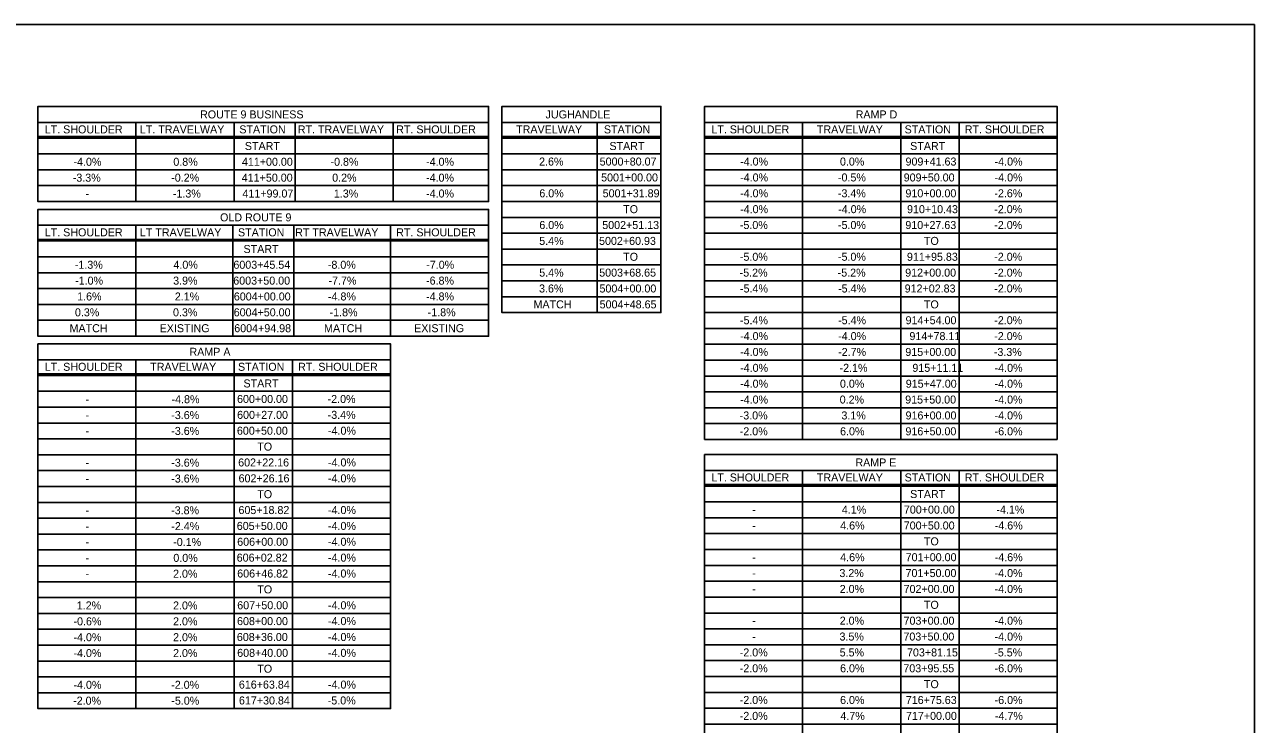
# Model space of a CAD drawing. Extents: x -15318841 to 1762012, y 465773 to 3693661.
# Drawn here: x -15314043.3 to -15313582.2, y 3693398.6 to 3693660.7 of the extents above; entities that cross this region are included whole.
import ezdxf

# ---------------------------------------------------------------- set-up
doc = ezdxf.new("R2010")
doc.units = 0
for name, color, linetype in [('BORDER', 7, 'Continuous'), ('Default', 7, 'Continuous'), ('DIMENSIONS', 7, 'Continuous')]:
    doc.layers.add(name, color=color, linetype=linetype)

msp = doc.modelspace()

# ---------------------------------------------------------------- linework, layer by layer
at = {"layer": 'BORDER'}
for p, q in [((-15314001.5, 3693624.08), (-15314001.5, 3693594.43)), ((-15313964.73, 3693624.08), (-15313964.73, 3693594.43)), ((-15313941.85, 3693624.08), (-15313941.85, 3693594.43)), ((-15313905.08, 3693624.08), (-15313905.08, 3693594.43)), ((-15313905.08, 3693624.08), (-15313905.08, 3693594.43)), ((-15313864.32, 3693624.08), (-15313864.32, 3693552.83)), ((-15313828.55, 3693624.08), (-15313828.55, 3693552.83)), ((-15313804.67, 3693624.08), (-15313804.67, 3693552.83)), ((-15313788.34, 3693624.08), (-15313788.34, 3693505.88)), ((-15313751.57, 3693624.08), (-15313751.57, 3693505.29)), ((-15313714.8, 3693624.08), (-15313714.8, 3693505.29)), ((-15313692.92, 3693624.08), (-15313692.92, 3693505.29)), ((-15314038.26, 3693618.8), (-15313869.32, 3693618.8)), ((-15314038.26, 3693618.2), (-15313869.32, 3693618.2)), ((-15313864.32, 3693618.8), (-15313804.67, 3693618.8)), ((-15313864.32, 3693618.2), (-15313804.67, 3693618.2)), ((-15313788.34, 3693618.8), (-15313656.16, 3693618.8)), ((-15313788.34, 3693618.2), (-15313656.16, 3693618.2)), ((-15314038.26, 3693612.26), (-15313869.32, 3693612.26)), ((-15314038.26, 3693612.26), (-15313869.32, 3693612.26)), ((-15314038.26, 3693612.26), (-15313869.32, 3693612.26)), ((-15313864.32, 3693612.26), (-15313804.67, 3693612.26)), ((-15313864.32, 3693612.26), (-15313804.67, 3693612.26)), ((-15313864.32, 3693612.26), (-15313804.67, 3693612.26)), ((-15313788.34, 3693612.26), (-15313656.16, 3693612.26)), ((-15313788.34, 3693612.26), (-15313656.16, 3693612.26)), ((-15313788.34, 3693612.26), (-15313656.16, 3693612.26)), ((-15314038.26, 3693606.32), (-15313869.32, 3693606.32)), ((-15313864.32, 3693606.32), (-15313804.67, 3693606.32)), ((-15313788.34, 3693606.32), (-15313656.16, 3693606.32)), ((-15314038.26, 3693600.38), (-15313869.32, 3693600.38)), ((-15313864.32, 3693600.38), (-15313804.67, 3693600.38)), ((-15313788.34, 3693600.38), (-15313656.16, 3693600.38)), ((-15313864.32, 3693594.43), (-15313804.67, 3693594.43)), ((-15313788.34, 3693594.43), (-15313656.16, 3693594.43)), ((-15313864.32, 3693588.49), (-15313804.67, 3693588.49)), ((-15313788.34, 3693588.49), (-15313656.16, 3693588.49)), ((-15314001.5, 3693585.52), (-15314001.5, 3693543.99)), ((-15313965.23, 3693585.52), (-15313965.23, 3693543.99)), ((-15313942.35, 3693585.52), (-15313942.35, 3693543.99)), ((-15313906.08, 3693585.52), (-15313906.08, 3693543.99)), ((-15314038.26, 3693580.24), (-15313869.32, 3693580.24)), ((-15314038.26, 3693579.64), (-15313869.32, 3693579.64)), ((-15313864.32, 3693582.55), (-15313804.67, 3693582.55)), ((-15313788.34, 3693582.55), (-15313656.16, 3693582.55)), ((-15314038.26, 3693573.7), (-15313869.32, 3693573.7)), ((-15314038.26, 3693573.7), (-15313869.32, 3693573.7)), ((-15314038.26, 3693573.7), (-15313869.32, 3693573.7)), ((-15313864.32, 3693576.6), (-15313804.67, 3693576.6)), ((-15313788.34, 3693576.6), (-15313656.16, 3693576.6)), ((-15313864.32, 3693570.66), (-15313804.67, 3693570.66)), ((-15313788.34, 3693570.66), (-15313656.16, 3693570.66)), ((-15314038.26, 3693567.76), (-15313869.32, 3693567.76)), ((-15313864.32, 3693564.72), (-15313804.67, 3693564.72)), ((-15313788.34, 3693564.72), (-15313656.16, 3693564.72)), ((-15314038.26, 3693561.81), (-15313869.32, 3693561.81)), ((-15314038.26, 3693555.87), (-15313869.32, 3693555.87)), ((-15313864.32, 3693558.78), (-15313804.67, 3693558.78)), ((-15313788.34, 3693558.78), (-15313656.16, 3693558.78)), ((-15313788.34, 3693552.83), (-15313656.16, 3693552.83)), ((-15314038.26, 3693549.93), (-15313869.32, 3693549.93)), ((-15313788.34, 3693546.89), (-15313656.16, 3693546.89)), ((-15313788.34, 3693540.95), (-15313656.16, 3693540.95)), ((-15314038.26, 3693535.16), (-15314038.26, 3693416.96)), ((-15314001.5, 3693535.16), (-15314001.5, 3693404.48)), ((-15313964.73, 3693535.16), (-15313964.73, 3693404.48)), ((-15313942.85, 3693535.16), (-15313942.85, 3693404.48)), ((-15313906.08, 3693535.16), (-15313906.08, 3693404.48)), ((-15313788.34, 3693535.01), (-15313656.16, 3693535.01)), ((-15314038.26, 3693529.87), (-15313906.08, 3693529.87)), ((-15314038.26, 3693529.28), (-15313906.08, 3693529.28)), ((-15313788.34, 3693529.06), (-15313656.16, 3693529.06)), ((-15314038.26, 3693523.34), (-15313906.08, 3693523.34)), ((-15314038.26, 3693523.34), (-15313906.08, 3693523.34)), ((-15314038.26, 3693523.34), (-15313906.08, 3693523.34)), ((-15313788.34, 3693523.12), (-15313656.16, 3693523.12)), ((-15314038.26, 3693517.39), (-15313906.08, 3693517.39)), ((-15313788.34, 3693517.18), (-15313656.16, 3693517.18)), ((-15314038.26, 3693511.45), (-15313906.08, 3693511.45)), ((-15313788.34, 3693511.24), (-15313656.16, 3693511.24)), ((-15314038.26, 3693505.51), (-15313906.08, 3693505.51)), ((-15314038.26, 3693499.57), (-15313906.08, 3693499.57)), ((-15314038.26, 3693493.62), (-15313906.08, 3693493.62)), ((-15313788.34, 3693493.72), (-15313788.34, 3693375.52)), ((-15313751.57, 3693493.72), (-15313751.57, 3693339.28)), ((-15313714.8, 3693493.72), (-15313714.8, 3693339.28)), ((-15313692.92, 3693493.72), (-15313692.92, 3693339.28)), ((-15314038.26, 3693487.68), (-15313906.08, 3693487.68)), ((-15313788.34, 3693488.44), (-15313656.16, 3693488.44)), ((-15313788.34, 3693487.84), (-15313656.16, 3693487.84)), ((-15314038.26, 3693481.74), (-15313906.08, 3693481.74)), ((-15313788.34, 3693481.9), (-15313656.16, 3693481.9)), ((-15313788.34, 3693481.9), (-15313656.16, 3693481.9)), ((-15313788.34, 3693481.9), (-15313656.16, 3693481.9)), ((-15314038.26, 3693475.79), (-15313906.08, 3693475.79)), ((-15313788.34, 3693475.96), (-15313656.16, 3693475.96)), ((-15314038.26, 3693469.85), (-15313906.08, 3693469.85)), ((-15313788.34, 3693470.02), (-15313656.16, 3693470.02)), ((-15314038.26, 3693463.91), (-15313906.08, 3693463.91)), ((-15313788.34, 3693464.07), (-15313656.16, 3693464.07)), ((-15313788.34, 3693458.13), (-15313656.16, 3693458.13)), ((-15314038.26, 3693457.97), (-15313906.08, 3693457.97)), ((-15314038.26, 3693452.02), (-15313906.08, 3693452.02)), ((-15313788.34, 3693452.19), (-15313656.16, 3693452.19)), ((-15314038.26, 3693446.08), (-15313906.08, 3693446.08)), ((-15313788.34, 3693446.24), (-15313656.16, 3693446.24)), ((-15314038.26, 3693440.14), (-15313906.08, 3693440.14)), ((-15313788.34, 3693440.3), (-15313656.16, 3693440.3)), ((-15314038.26, 3693434.2), (-15313906.08, 3693434.2)), ((-15313788.34, 3693434.36), (-15313656.16, 3693434.36)), ((-15314038.26, 3693428.25), (-15313906.08, 3693428.25)), ((-15313788.34, 3693428.42), (-15313656.16, 3693428.42)), ((-15314038.26, 3693422.31), (-15313906.08, 3693422.31)), ((-15313788.34, 3693422.47), (-15313656.16, 3693422.47)), ((-15314038.26, 3693416.37), (-15313906.08, 3693416.37)), ((-15313788.34, 3693416.53), (-15313656.16, 3693416.53)), ((-15314038.26, 3693410.42), (-15313906.08, 3693410.42)), ((-15313788.34, 3693410.59), (-15313656.16, 3693410.59)), ((-15313788.34, 3693404.65), (-15313656.16, 3693404.65)), ((-15313788.34, 3693398.7), (-15313656.16, 3693398.7))]:
    msp.add_line(p, q, dxfattribs=at)
for points in [[(-15314038.26, 3693624.08), (-15314038.26, 3693630.02), (-15313869.32, 3693630.02), (-15313869.32, 3693624.08)], [(-15313864.32, 3693624.08), (-15313864.32, 3693630.02), (-15313804.67, 3693630.02), (-15313804.67, 3693624.08)], [(-15313788.34, 3693624.08), (-15313788.34, 3693630.02), (-15313656.16, 3693630.02), (-15313656.16, 3693624.08)], [(-15314038.26, 3693585.52), (-15314038.26, 3693591.46), (-15313869.32, 3693591.46), (-15313869.32, 3693585.52)], [(-15314038.26, 3693535.16), (-15314038.26, 3693541.1), (-15313906.08, 3693541.1), (-15313906.08, 3693535.16)], [(-15313788.34, 3693493.72), (-15313788.34, 3693499.66), (-15313656.16, 3693499.66), (-15313656.16, 3693493.72)]]:
    msp.add_lwpolyline(points, dxfattribs=at)
for points in [[(-15314038.26, 3693624.08), (-15313869.32, 3693624.08), (-15313869.32, 3693594.43), (-15314038.26, 3693594.43)], [(-15313864.32, 3693624.08), (-15313804.67, 3693624.08), (-15313804.67, 3693552.83), (-15313864.32, 3693552.83)], [(-15313788.34, 3693624.08), (-15313656.16, 3693624.08), (-15313656.16, 3693505.29), (-15313788.34, 3693505.29)], [(-15314038.26, 3693585.52), (-15313869.32, 3693585.52), (-15313869.32, 3693543.99), (-15314038.26, 3693543.99)], [(-15314038.26, 3693535.16), (-15313906.08, 3693535.16), (-15313906.08, 3693404.48), (-15314038.26, 3693404.48)], [(-15313788.34, 3693493.72), (-15313656.16, 3693493.72), (-15313656.16, 3693339.28), (-15313788.34, 3693339.28)]]:
    msp.add_lwpolyline(points, close=True, dxfattribs=at)
at = {"layer": 'Default'}
msp.add_lwpolyline([(-15314452.76, 3693660.68), (-15313582.2, 3693660.68), (-15313582.2, 3693071.2), (-15314452.76, 3693071.2)], close=True, dxfattribs=at)

# ---------------------------------------------------------------- texts
at = {"layer": 'DIMENSIONS'}
for s, p in [('ROUTE 9 BUSINESS', (-15313977.48, 3693625.55)), ('JUGHANDLE', (-15313847.94, 3693625.55)), ('RAMP D', (-15313731.68, 3693625.55)), ('LT. SHOULDER', (-15314035.71, 3693619.94)), ('LT. TRAVELWAY', (-15314000.04, 3693619.94)), ('STATION', (-15313962.76, 3693619.94)), ('RT. TRAVELWAY', (-15313940.83, 3693619.94)), ('RT. SHOULDER', (-15313903.96, 3693619.94)), ('TRAVELWAY', (-15313858.99, 3693619.94)), ('STATION', (-15313826.08, 3693619.94)), ('LT. SHOULDER', (-15313785.78, 3693619.94)), ('TRAVELWAY', (-15313746.24, 3693619.94)), ('STATION', (-15313713.34, 3693619.94)), ('RT. SHOULDER', (-15313690.8, 3693619.94)), ('START', (-15313960.69, 3693613.72)), ('START', (-15313824.01, 3693613.72)), ('START', (-15313711.26, 3693613.72)), ('-4.0%', (-15314024.93, 3693607.81)), ('0.8%', (-15313987.5, 3693607.81)), ('411+00.00', (-15313961.79, 3693607.81)), ('-0.8%', (-15313928.57, 3693607.81)), ('-4.0%', (-15313892.75, 3693607.81)), ('2.6%', (-15313850.37, 3693607.89)), ('5000+80.07', (-15313827.66, 3693607.89)), ('-4.0%', (-15313775, 3693607.89)), ('0.0%', (-15313737.58, 3693607.89)), ('909+41.63', (-15313712.99, 3693607.89)), ('-4.0%', (-15313679.59, 3693607.89)), ('-3.3%', (-15314025.21, 3693601.86)), ('-0.2%', (-15313988.3, 3693601.86)), ('411+50.00', (-15313961.84, 3693601.86)), ('0.2%', (-15313927.95, 3693601.86)), ('-4.0%', (-15313892.75, 3693601.86)), ('5001+00.00', (-15313827.12, 3693601.94)), ('-4.0%', (-15313775, 3693601.94)), ('-0.5%', (-15313738.33, 3693601.94)), ('909+50.00', (-15313713.68, 3693601.94)), ('-4.0%', (-15313679.59, 3693601.94)), ('-', (-15314020.39, 3693595.92)), ('-1.3%', (-15313987.67, 3693595.92)), ('411+99.07', (-15313961.58, 3693595.92)), ('1.3%', (-15313927.32, 3693595.92)), ('-4.0%', (-15313892.75, 3693595.92)), ('6.0%', (-15313850.28, 3693596)), ('5001+31.89', (-15313826.53, 3693596)), ('-4.0%', (-15313775, 3693596)), ('-3.4%', (-15313738.35, 3693596)), ('910+00.00', (-15313713.02, 3693596)), ('-2.6%', (-15313679.69, 3693596)), ('TO', (-15313818.85, 3693590.06)), ('-4.0%', (-15313775, 3693590.06)), ('-4.0%', (-15313738.24, 3693590.06)), ('910+10.43', (-15313712.42, 3693590.06)), ('-2.0%', (-15313679.73, 3693590.06)), ('OLD ROUTE 9', (-15313969.98, 3693586.99)), ('LT. SHOULDER', (-15314035.71, 3693581.38)), ('LT TRAVELWAY', (-15314000.04, 3693581.38)), ('STATION', (-15313963.26, 3693581.38)), ('RT TRAVELWAY', (-15313941.83, 3693581.38)), ('RT. SHOULDER', (-15313903.96, 3693581.38)), ('6.0%', (-15313850.28, 3693584.12)), ('5002+51.13', (-15313826.7, 3693584.12)), ('-5.0%', (-15313775.1, 3693584.12)), ('-5.0%', (-15313738.33, 3693584.12)), ('910+27.63', (-15313713.06, 3693584.12)), ('-2.0%', (-15313679.73, 3693584.12)), ('START', (-15313961.19, 3693575.15)), ('5.4%', (-15313850.32, 3693578.17)), ('5002+60.93', (-15313827.89, 3693578.17)), ('TO', (-15313706.1, 3693578.17)), ('TO', (-15313818.85, 3693572.23)), ('-5.0%', (-15313775.1, 3693572.23)), ('-5.0%', (-15313738.33, 3693572.23)), ('911+95.83', (-15313712.47, 3693572.23)), ('-2.0%', (-15313679.73, 3693572.23)), ('-1.3%', (-15314024.43, 3693569.24)), ('4.0%', (-15313987.46, 3693569.24)), ('6003+45.54', (-15313964.98, 3693569.24)), ('-8.0%', (-15313929.57, 3693569.24)), ('-7.0%', (-15313892.68, 3693569.24)), ('5.4%', (-15313850.32, 3693566.29)), ('5003+68.65', (-15313827.84, 3693566.29)), ('-5.2%', (-15313775.19, 3693566.29)), ('-5.2%', (-15313738.43, 3693566.29)), ('912+00.00', (-15313713.12, 3693566.29)), ('-2.0%', (-15313679.73, 3693566.29)), ('-1.0%', (-15314024.32, 3693563.3)), ('3.9%', (-15313987.57, 3693563.3)), ('6003+50.00', (-15313965.03, 3693563.3)), ('-7.7%', (-15313929.33, 3693563.3)), ('-6.8%', (-15313892.75, 3693563.3)), ('1.6%', (-15314023.56, 3693557.36)), ('2.1%', (-15313986.94, 3693557.36)), ('6004+00.00', (-15313964.82, 3693557.36)), ('-4.8%', (-15313929.52, 3693557.36)), ('-4.8%', (-15313892.75, 3693557.36)), ('3.6%', (-15313850.39, 3693560.35)), ('5004+00.00', (-15313827.73, 3693560.35)), ('-5.4%', (-15313775.05, 3693560.35)), ('-5.4%', (-15313738.28, 3693560.35)), ('912+02.83', (-15313713.32, 3693560.35)), ('-2.0%', (-15313679.73, 3693560.35)), ('MATCH', (-15313852.46, 3693554.4)), ('5004+48.65', (-15313827.67, 3693554.4)), ('TO', (-15313706.1, 3693554.4)), ('0.3%', (-15314024.39, 3693551.42)), ('0.3%', (-15313987.62, 3693551.42)), ('6004+50.00', (-15313964.86, 3693551.42)), ('-1.8%', (-15313928.91, 3693551.42)), ('-1.8%', (-15313892.14, 3693551.42)), ('-5.4%', (-15313775.05, 3693548.46)), ('-5.4%', (-15313738.28, 3693548.46)), ('914+54.00', (-15313712.98, 3693548.46)), ('-2.0%', (-15313679.73, 3693548.46)), ('MATCH', (-15314026.4, 3693545.47)), ('EXISTING', (-15313992.64, 3693545.47)), ('6004+94.98', (-15313964.66, 3693545.47)), ('MATCH', (-15313930.99, 3693545.47)), ('EXISTING', (-15313897.22, 3693545.47)), ('-4.0%', (-15313775, 3693542.52)), ('-4.0%', (-15313738.24, 3693542.52)), ('914+78.11', (-15313711.53, 3693542.52)), ('-2.0%', (-15313679.73, 3693542.52)), ('RAMP A', (-15313981.45, 3693536.63)), ('-4.0%', (-15313775, 3693536.58)), ('-2.7%', (-15313738.26, 3693536.58)), ('915+00.00', (-15313713.07, 3693536.58)), ('-3.3%', (-15313679.88, 3693536.58)), ('LT. SHOULDER', (-15314035.71, 3693531.02)), ('TRAVELWAY', (-15313996.17, 3693531.02)), ('STATION', (-15313963.26, 3693531.02)), ('RT. SHOULDER', (-15313940.73, 3693531.02)), ('-4.0%', (-15313775, 3693530.63)), ('-2.1%', (-15313737.72, 3693530.63)), ('915+11.11', (-15313710.42, 3693530.63)), ('-4.0%', (-15313679.59, 3693530.63)), ('START', (-15313961.19, 3693524.79)), ('-4.0%', (-15313775, 3693524.69)), ('0.0%', (-15313737.58, 3693524.69)), ('915+47.00', (-15313712.9, 3693524.69)), ('-4.0%', (-15313679.59, 3693524.69)), ('-', (-15314020.39, 3693518.88)), ('-4.8%', (-15313988.16, 3693518.88)), ('600+00.00', (-15313963.61, 3693518.96)), ('-2.0%', (-15313929.66, 3693518.96)), ('-4.0%', (-15313775, 3693518.75)), ('0.2%', (-15313737.67, 3693518.75)), ('915+50.00', (-15313713.12, 3693518.75)), ('-4.0%', (-15313679.59, 3693518.75)), ('-', (-15314020.39, 3693512.94)), ('-3.6%', (-15313988.28, 3693512.94)), ('600+27.00', (-15313963.59, 3693513.02)), ('-3.4%', (-15313929.64, 3693513.02)), ('-3.0%', (-15313775.17, 3693512.8)), ('3.1%', (-15313737.03, 3693512.8)), ('916+00.00', (-15313712.98, 3693512.8)), ('-4.0%', (-15313679.59, 3693512.8)), ('-3.6%', (-15313988.28, 3693507)), ('600+50.00', (-15313963.66, 3693507.08)), ('-4.0%', (-15313929.52, 3693507.08)), ('-2.0%', (-15313775.15, 3693506.86)), ('6.0%', (-15313737.53, 3693506.86)), ('916+50.00', (-15313713.02, 3693506.86)), ('-6.0%', (-15313679.59, 3693506.86)), ('-', (-15314020.39, 3693507)), ('TO', (-15313956.03, 3693501.13)), ('-', (-15314020.39, 3693495.11)), ('-3.6%', (-15313988.28, 3693495.11)), ('602+22.16', (-15313963.19, 3693495.19)), ('-4.0%', (-15313929.52, 3693495.19)), ('RAMP E', (-15313731.79, 3693495.19)), ('-', (-15314020.39, 3693489.17)), ('-3.6%', (-15313988.28, 3693489.17)), ('602+26.16', (-15313963.04, 3693489.25)), ('-4.0%', (-15313929.52, 3693489.25)), ('LT. SHOULDER', (-15313785.78, 3693489.58)), ('TRAVELWAY', (-15313746.24, 3693489.58)), ('STATION', (-15313713.34, 3693489.58)), ('RT. SHOULDER', (-15313690.8, 3693489.58)), ('TO', (-15313956.03, 3693483.31)), ('START', (-15313711.26, 3693483.36)), ('-', (-15314020.39, 3693477.28)), ('-3.8%', (-15313988.33, 3693477.28)), ('605+18.82', (-15313963.08, 3693477.36)), ('-4.0%', (-15313929.52, 3693477.36)), ('-', (-15313770.46, 3693477.53)), ('4.1%', (-15313736.87, 3693477.53)), ('700+00.00', (-15313713.61, 3693477.53)), ('-4.1%', (-15313678.93, 3693477.53)), ('-', (-15314020.39, 3693471.34)), ('-2.4%', (-15313988.26, 3693471.34)), ('605+50.00', (-15313963.71, 3693471.42)), ('-4.0%', (-15313929.52, 3693471.42)), ('-', (-15313770.46, 3693471.58)), ('4.6%', (-15313737.48, 3693471.58)), ('700+50.00', (-15313713.66, 3693471.58)), ('-4.6%', (-15313679.55, 3693471.58)), ('-0.1%', (-15313987.55, 3693465.4)), ('606+00.00', (-15313963.56, 3693465.48)), ('-4.0%', (-15313929.52, 3693465.48)), ('TO', (-15313706.1, 3693465.64)), ('-', (-15314020.39, 3693465.4)), ('4.6%', (-15313737.48, 3693459.7)), ('701+00.00', (-15313712.95, 3693459.7)), ('-4.6%', (-15313679.55, 3693459.7)), ('-', (-15314020.39, 3693459.45)), ('0.0%', (-15313987.5, 3693459.45)), ('606+02.82', (-15313963.74, 3693459.54)), ('-4.0%', (-15313929.52, 3693459.54)), ('-', (-15313770.46, 3693459.7)), ('-', (-15314020.39, 3693453.51)), ('2.0%', (-15313987.6, 3693453.51)), ('606+46.82', (-15313963.55, 3693453.59)), ('-4.0%', (-15313929.52, 3693453.59)), ('-', (-15313770.46, 3693453.76)), ('3.2%', (-15313737.79, 3693453.76)), ('701+50.00', (-15313713, 3693453.76)), ('-4.0%', (-15313679.59, 3693453.76)), ('TO', (-15313956.03, 3693447.65)), ('-', (-15313770.46, 3693447.81)), ('2.0%', (-15313737.67, 3693447.81)), ('702+00.00', (-15313713.71, 3693447.81)), ('-4.0%', (-15313679.59, 3693447.81)), ('1.2%', (-15314023.7, 3693441.63)), ('2.0%', (-15313987.6, 3693441.63)), ('607+50.00', (-15313963.54, 3693441.71)), ('-4.0%', (-15313929.52, 3693441.71)), ('TO', (-15313706.1, 3693441.87)), ('-0.6%', (-15314024.93, 3693435.68)), ('2.0%', (-15313987.6, 3693435.68)), ('608+00.00', (-15313963.61, 3693435.77)), ('-4.0%', (-15313929.52, 3693435.77)), ('-', (-15313770.46, 3693435.93)), ('2.0%', (-15313737.67, 3693435.93)), ('703+00.00', (-15313713.73, 3693435.93)), ('-4.0%', (-15313679.59, 3693435.93)), ('-4.0%', (-15314024.93, 3693429.74)), ('2.0%', (-15313987.6, 3693429.74)), ('608+36.00', (-15313963.68, 3693429.82)), ('-4.0%', (-15313929.52, 3693429.82)), ('-', (-15313770.46, 3693429.99)), ('3.5%', (-15313737.74, 3693429.99)), ('703+50.00', (-15313713.78, 3693429.99)), ('-4.0%', (-15313679.59, 3693429.99)), ('-4.0%', (-15314024.93, 3693423.8)), ('2.0%', (-15313987.6, 3693423.8)), ('608+40.00', (-15313963.56, 3693423.88)), ('-4.0%', (-15313929.52, 3693423.88)), ('-2.0%', (-15313775.15, 3693424.04)), ('5.5%', (-15313737.67, 3693424.04)), ('703+81.15', (-15313712.44, 3693424.04)), ('-5.5%', (-15313679.73, 3693424.04)), ('TO', (-15313956.03, 3693417.94)), ('-2.0%', (-15313775.15, 3693418.1)), ('6.0%', (-15313737.53, 3693418.1)), ('703+95.55', (-15313713.81, 3693418.1)), ('-6.0%', (-15313679.59, 3693418.1)), ('-4.0%', (-15314024.93, 3693411.91)), ('-2.0%', (-15313988.3, 3693411.91)), ('616+63.84', (-15313962.93, 3693411.99)), ('-4.0%', (-15313929.52, 3693411.99)), ('TO', (-15313706.1, 3693412.16)), ('-2.0%', (-15314025.07, 3693405.97)), ('-5.0%', (-15313988.26, 3693405.97)), ('617+30.84', (-15313962.9, 3693406.05)), ('-5.0%', (-15313929.61, 3693406.05)), ('-2.0%', (-15313775.15, 3693406.22)), ('6.0%', (-15313737.53, 3693406.22)), ('716+75.63', (-15313712.89, 3693406.22)), ('-6.0%', (-15313679.59, 3693406.22)), ('-2.0%', (-15313775.15, 3693400.27)), ('4.7%', (-15313737.41, 3693400.27)), ('717+00.00', (-15313712.83, 3693400.27)), ('-4.7%', (-15313679.47, 3693400.27))]:
    msp.add_text(s, height=3, dxfattribs=at).set_placement(p)

doc.saveas('drawing.dxf')
